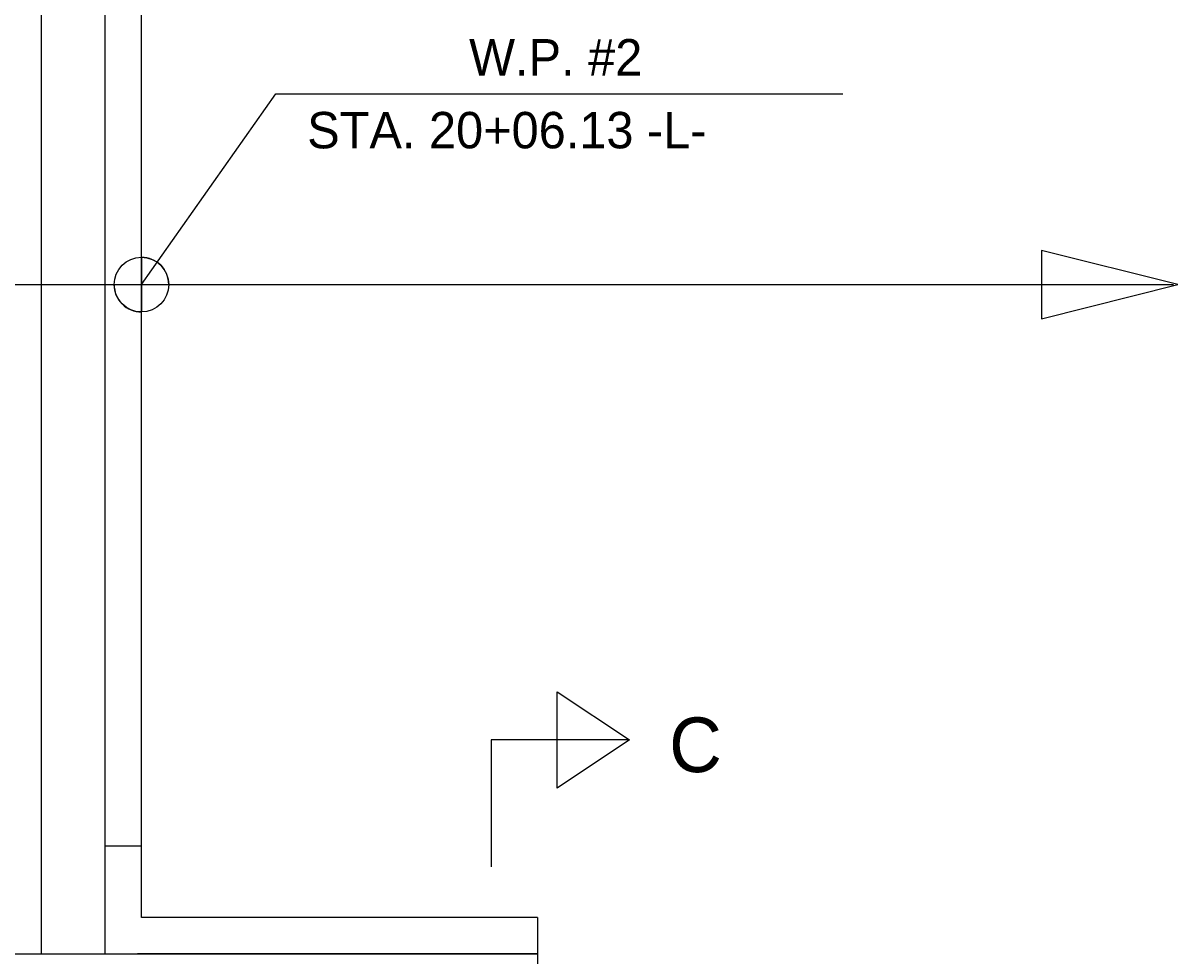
# Model space of a CAD drawing. Extents: x 0 to 265, y -200 to 22.
# Drawn here: x 145.25 to 176.95, y -76.78 to -51.17 of the extents above; entities that cross this region are included whole.
import ezdxf

# ---------------------------------------------------------------- set-up
doc = ezdxf.new("R2010")
doc.units = 0
for name, color, linetype in [('Arrowhead Terminators CELL', 7, 'Continuous'), ('Default', 7, 'Continuous'), ('Dimension Lines', 7, 'Continuous'), ('Mis -L- Lines', 7, 'Continuous'), ('Mis Object Lines', 7, 'Continuous'), ('Mis Work Point CELL', 7, 'Continuous'), ('Subtitle Text', 7, 'Continuous'), ('Sup Concrete Girder Lines', 7, 'Continuous'), ('Text', 7, 'Continuous')]:
    doc.layers.add(name, color=color, linetype=linetype)

msp = doc.modelspace()

# ---------------------------------------------------------------- linework, layer by layer
at = {"layer": 'Arrowhead Terminators CELL'}
for points in [[(176.955, -58.349), (173.205, -57.412), (173.205, -59.287)], [(161.894, -70.849), (159.91, -72.172), (159.91, -69.527)], [(161.894, -70.849), (159.91, -72.172), (159.91, -69.527)]]:
    msp.add_lwpolyline(points, close=True, dxfattribs=at)
at = {"layer": 'Default'}
msp.add_line((148.386, -76.722), (158.386, -76.722), dxfattribs=at)
at = {"layer": 'Dimension Lines'}
for p, q in [((148.496, -58.349), (152.182, -53.107)), ((152.182, -53.107), (167.754, -53.107))]:
    msp.add_line(p, q, dxfattribs=at)
for points in [[(158.1, -70.849), (158.1, -74.329)], [(161.894, -70.849), (158.1, -70.849)]]:
    msp.add_lwpolyline(points, dxfattribs=at)
at = {"layer": 'Mis -L- Lines'}
msp.add_line((49.574, -58.349), (176.83, -58.349), dxfattribs=at)
at = {"layer": 'Mis Object Lines'}
for p, q in [((147.496, -76.722), (147.496, -39.933)), ((148.496, -75.722), (148.496, -40.933)), ((145.746, -43.496), (145.746, -76.722)), ((148.496, -73.766), (147.496, -73.766)), ((159.366, -75.722), (148.496, -75.722)), ((159.366, -75.722), (159.366, -76.722)), ((144.746, -76.722), (159.366, -76.722))]:
    msp.add_line(p, q, dxfattribs=at)
at = {"layer": 'Mis Work Point CELL'}
for p, q in [((148.496, -57.599), (148.496, -58.349)), ((147.746, -58.349), (148.496, -58.349)), ((148.496, -58.349), (148.496, -59.099)), ((148.496, -58.349), (149.246, -58.349)), ((149.246, -58.349), (149.246, -58.349)), ((148.496, -59.099), (148.496, -59.099))]:
    msp.add_line(p, q, dxfattribs=at)
msp.add_circle((148.496, -58.349), 0.75, dxfattribs=at)
for start, end in [(359.997, 89.9989), (180.0011, 270.003)]:
    msp.add_arc((148.496, -58.349), 0.75, start, end, dxfattribs=at)
at = {"layer": 'Sup Concrete Girder Lines'}
for p, q in [((159.386, -76.722), (148.386, -76.722)), ((159.366, -76.722), (159.366, -97.349))]:
    msp.add_line(p, q, dxfattribs=at)
at = {"layer": 'Text'}
msp.add_line((148.496, -58.349), (148.496, -58.349), dxfattribs=at)
msp.add_line((148.496, -58.349), (148.496, -58.349), dxfattribs=at)

# ---------------------------------------------------------------- texts
at = {"layer": 'Subtitle Text'}
msp.add_text('C', height=1.5, dxfattribs=at).set_placement((162.985, -71.733))
at = {"layer": 'Text'}
for s, p in [('W.P. #2', (157.492, -52.607)), ('STA. 20+06.13 -L-', (153.047, -54.607))]:
    msp.add_text(s, height=1, dxfattribs=at).set_placement(p)

doc.saveas('drawing.dxf')
